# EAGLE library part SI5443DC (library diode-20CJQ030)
Vishay Siliconix's Si5443DC P-Channel 2.5-V (G-S) MOSFET Please send any comments to: messi@users.sourceforge.net
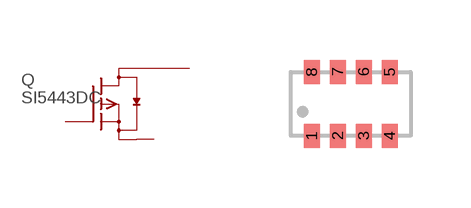
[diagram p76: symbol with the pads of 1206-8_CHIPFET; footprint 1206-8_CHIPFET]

Designator prefix Q

## SI5443DC  [1206-8_CHIPFET]
1  D  pas
2  D  pas
3  D  pas
4  G  pas
5  S  pas
6  D  pas
7  D  pas
8  D  pas

## Footprint 1206-8_CHIPFET (pad centres in mm)
Used in Si5443DC
smd 0.4 x 0.6: 1 -0.975,-0.8; 2 -0.325,-0.8; 3 0.325,-0.8; 4 0.975,-0.8; 5 0.975,0.8; 6 0.325,0.8; 7 -0.325,0.8; 8 -0.975,0.8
